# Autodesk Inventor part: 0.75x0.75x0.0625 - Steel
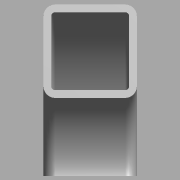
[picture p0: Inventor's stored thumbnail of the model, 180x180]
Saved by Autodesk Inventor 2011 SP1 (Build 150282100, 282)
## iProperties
Created: 2011-03
Part Number: 0.75x0.75x0.0625 - Steel
Material: Default
Document SubType Name: Modeling
Designer: bamfomg
Density: 1 g/cm^3
Author: bamfomg
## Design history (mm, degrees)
derived "Square Tube Corners.ipt" dims "d2" = 9.525, "d3" = 9.525, "d6" = 1.5875, "d7" = 1.5875, "d8" = 1.5875, "d12" = 90 deg, "d16" = 1.5875, "d18" = 30 deg, "ID_Rad" = 0.79375, "OD_Rad" = 2.38125, "Side_One" = 19.05, "Side_Two" = 19.05, "Thickness" = 1.5875, "Bend_IDRad" = 15.875, "Bevel_Angl" = 30 deg, "Bevel_Dist" = 1.5875
body "Solid1"
feature "Solid1::Square Tube Corners.ipt" dims "d2" = 9.525, "d3" = 9.525, "d6" = 1.5875, "d7" = 1.5875, "d8" = 1.5875, "d12" = 90 deg, "d16" = 1.5875, "d18" = 30 deg, "ID_Rad" = 0.79375, "OD_Rad" = 2.38125, "Side_One" = 19.05, "Side_Two" = 19.05, "Thickness" = 1.5875, "Bend_IDRad" = 15.875, "Bevel_Angl" = 30 deg, "Bevel_Dist" = 1.5875, "ScaleForDerivedMember" = 10
tag "TaggingFeature1"
